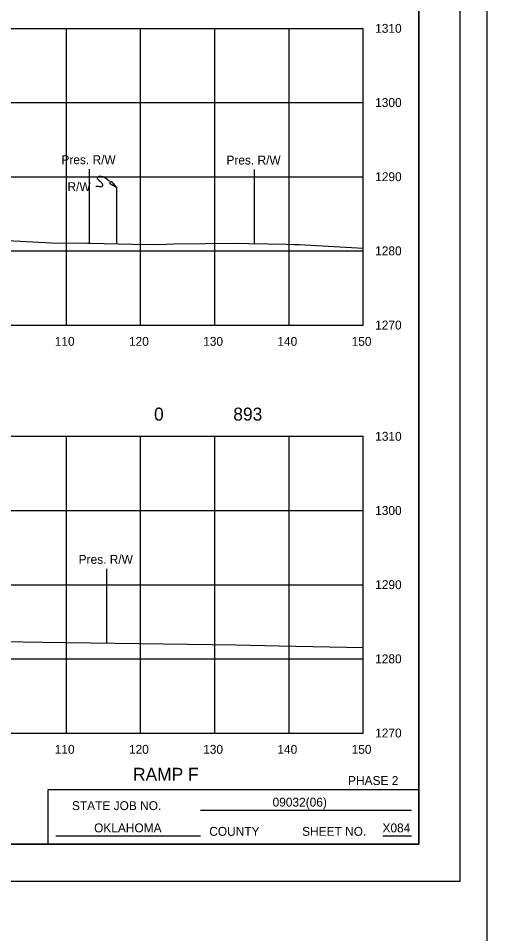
# Model space of a CAD drawing. Extents: x 2148105 to 2149976, y 144169 to 149705.
# Drawn here: x 2148516.8 to 2148579.9, y 144909.9 to 145033.3 of the extents above; entities that cross this region are included whole.
import ezdxf

# ---------------------------------------------------------------- set-up
doc = ezdxf.new("R2010")
doc.units = 0
for name, color, linetype in [('PH1a-PR-ServRd', 7, 'Continuous'), ('PR_Align_Ramp_A', 7, 'Continuous'), ('PR_Align_Ramp_E', 7, 'Continuous'), ('PR_Align_Ramp_F', 7, 'Continuous'), ('PR_Align_Ramp_J', 7, 'Continuous'), ('PR_Align_Retaining_Wall_C', 7, 'Continuous'), ('PR_Storm_Conc_Box_PH1B', 7, 'Continuous'), ('PR_Storm_Conc_Pipe_PH1B', 7, 'Continuous'), ('PR_Storm_Inlet_CICI_PH1B', 7, 'Continuous'), ('PR_Storm_MH_PH1A', 7, 'Continuous'), ('PR_Storm_MH_PH1B', 7, 'Continuous'), ('PR_Storm_Standard_Median_Drain_PH1B', 7, 'Continuous'), ('TOPO_BRIDGE_Low Beam', 7, 'Continuous')]:
    doc.layers.add(name, color=color, linetype=linetype)

msp = doc.modelspace()

# ---------------------------------------------------------------- linework, layer by layer
at = {"layer": 'PH1a-PR-ServRd'}
for p, q in [((2148520.88, 144921.91), (2148520.88, 144929.3)), ((2148520.88, 144929.3), (2148570.82, 144929.3))]:
    msp.add_line(p, q, dxfattribs=at)
msp.add_lwpolyline([(2148570.82, 144921.91), (2148255.82, 144921.91), (2148255.82, 145131.91), (2148570.82, 145131.91)], close=True, dxfattribs=at)
at = {"layer": 'PR_Align_Ramp_E'}
msp.add_lwpolyline([(2148219.95, 145145.16), (2148579.95, 145145.16), (2148579.95, 144905.16), (2148219.95, 144905.16)], close=True, dxfattribs=at)
at = {"layer": 'PR_Align_Ramp_J'}
msp.add_lwpolyline([(2148236.32, 145136.91), (2148576.32, 145136.91), (2148576.32, 144916.91), (2148236.32, 144916.91)], close=True, dxfattribs=at)
at = {"layer": 'PR_Align_Retaining_Wall_C'}
for p, q in [((2148541.37, 144926.52), (2148569.82, 144926.52)), ((2148521.88, 144923.05), (2148541.37, 144923.05)), ((2148565.97, 144923.05), (2148569.82, 144923.05))]:
    msp.add_line(p, q, dxfattribs=at)
at = {"layer": 'PR_Storm_Conc_Box_PH1B'}
for p, q in [((2148263.32, 145031.91), (2148563.32, 145031.91)), ((2148523.32, 144991.91), (2148523.32, 145031.91)), ((2148533.32, 144991.91), (2148533.32, 145031.91)), ((2148543.32, 144991.91), (2148543.32, 145031.91)), ((2148553.32, 144991.91), (2148553.32, 145031.91)), ((2148563.32, 144991.91), (2148563.32, 145031.91)), ((2148263.32, 145021.91), (2148563.32, 145021.91)), ((2148263.32, 145011.91), (2148563.32, 145011.91)), ((2148263.32, 145001.91), (2148563.32, 145001.91)), ((2148263.32, 144991.91), (2148563.32, 144991.91)), ((2148263.32, 144976.91), (2148563.32, 144976.91)), ((2148523.32, 144936.91), (2148523.32, 144976.91)), ((2148533.32, 144936.91), (2148533.32, 144976.91)), ((2148543.32, 144936.91), (2148543.32, 144976.91)), ((2148553.32, 144936.91), (2148553.32, 144976.91)), ((2148563.32, 144936.91), (2148563.32, 144976.91)), ((2148263.32, 144966.91), (2148563.32, 144966.91)), ((2148263.32, 144956.91), (2148563.32, 144956.91)), ((2148263.32, 144946.91), (2148563.32, 144946.91)), ((2148263.32, 144936.91), (2148563.32, 144936.91))]:
    msp.add_line(p, q, dxfattribs=at)
at = {"layer": 'PR_Storm_Conc_Pipe_PH1B'}
msp.add_lwpolyline([(2148255.82, 144921.91), (2148570.82, 144921.91), (2148570.82, 145131.91), (2148255.82, 145131.91)], close=True, dxfattribs=at)
msp.add_lwpolyline([(2148255.82, 144921.91), (2148570.82, 144921.91), (2148570.82, 145131.91), (2148255.82, 145131.91)], close=True, dxfattribs=at)
at = {"layer": 'PR_Storm_Inlet_CICI_PH1B'}
for points in [[(2148513.64, 145003.39), (2148521.31, 145003.01), (2148526.18, 145002.94), (2148526.53, 145002.93), (2148532.23, 145002.83), (2148535.83, 145002.79), (2148537.81, 145002.84), (2148546.22, 145002.93), (2148547.9, 145002.9), (2148553.04, 145002.8), (2148554.01, 145002.77), (2148554.69, 145002.76), (2148563.32, 145002.27)], [(2148383.92, 144951.36), (2148393.36, 144951.11), (2148395.33, 144950.69), (2148395.77, 144950.58), (2148397.19, 144950.58), (2148404.66, 144950.58), (2148427.82, 144950.58), (2148427.82, 144950.58), (2148428.89, 144950.55), (2148429.62, 144950.53), (2148458.36, 144949.75), (2148458.82, 144949.84), (2148460.86, 144950.23), (2148465.15, 144950.18), (2148481.59, 144949.82), (2148493.11, 144949.63), (2148504.69, 144949.36), (2148514.84, 144949.25), (2148520.1, 144949.18), (2148546.13, 144948.8), (2148552.01, 144948.65), (2148563.32, 144948.42)]]:
    msp.add_lwpolyline(points, dxfattribs=at)
at = {"layer": 'PR_Storm_MH_PH1A'}
for p, q in [((2148526.45, 145002.94), (2148526.45, 145012.94)), ((2148548.68, 145002.88), (2148548.68, 145012.88)), ((2148528.77, 144949.06), (2148528.77, 144959.06))]:
    msp.add_line(p, q, dxfattribs=at)
at = {"layer": 'PR_Storm_Standard_Median_Drain_PH1B'}
for p, q in [((2148563.32, 144991.91), (2148563.32, 145031.91)), ((2148263.32, 144991.91), (2148563.32, 144991.91)), ((2148563.32, 144936.91), (2148563.32, 144976.91)), ((2148263.32, 144936.91), (2148563.32, 144936.91))]:
    msp.add_line(p, q, dxfattribs=at)
at = {"layer": 'TOPO_BRIDGE_Low Beam'}
msp.add_line((2148530.13, 145002.87), (2148530.13, 145010.47), dxfattribs=at)
for points in [[(2148529.12, 145011.28), (2148528.77, 145011.57), (2148528.6, 145011.7), (2148528.51, 145011.77), (2148528.41, 145011.83), (2148528.31, 145011.88), (2148528.19, 145011.91), (2148528.06, 145011.94), (2148527.97, 145011.95), (2148527.88, 145011.95), (2148527.8, 145011.95), (2148527.73, 145011.93), (2148527.68, 145011.92), (2148527.62, 145011.9), (2148527.58, 145011.87), (2148527.54, 145011.84), (2148527.51, 145011.8), (2148527.48, 145011.74), (2148527.48, 145011.68), (2148527.49, 145011.64), (2148527.54, 145011.57), (2148527.73, 145011.41), (2148527.92, 145011.25), (2148528, 145011.17), (2148528.06, 145011.1), (2148528.12, 145011), (2148528.16, 145010.94), (2148528.2, 145010.85), (2148528.2, 145010.78), (2148528.18, 145010.69), (2148528.14, 145010.62), (2148528.09, 145010.59), (2148528.03, 145010.56), (2148527.92, 145010.55), (2148527.79, 145010.56), (2148527.63, 145010.57), (2148527.3, 145010.61)], [(2148530.13, 145010.47), (2148529.61, 145011.02), (2148529.35, 145011.33), (2148529.27, 145011.16), (2148529.13, 145011.04), (2148530.13, 145010.47)]]:
    msp.add_lwpolyline(points, dxfattribs=at)

# ---------------------------------------------------------------- texts
at = {"layer": 'PR_Align_Ramp_A'}
for s, p in [('0', (2148535.13, 144979.03)), ('893', (2148545.81, 144979.03))]:
    msp.add_text(s, height=1.75, dxfattribs=at).set_placement(p)
at = {"layer": 'PR_Align_Ramp_F'}
for s, height, p in [('RAMP F', 1.75, (2148532.3, 144930.47)), ('PHASE 2', 1.2, (2148561.27, 144929.9)), ('09032(06)', 1.2, (2148551.1, 144926.99)), ('STATE JOB NO.', 1.2, (2148524.07, 144926.52)), ('OKLAHOMA', 1.2, (2148527.05, 144923.52)), ('COUNTY', 1.2, (2148542.57, 144923.05)), ('SHEET NO.', 1.2, (2148555.08, 144923.05)), ('X084', 1.2, (2148565.91, 144923.52))]:
    msp.add_text(s, height=height, dxfattribs=at).set_placement(p)
at = {"layer": 'PR_Storm_MH_PH1A'}
for p in [(2148522.65, 145013.6), (2148544.88, 145013.55), (2148524.97, 144959.72)]:
    msp.add_text('Pres. R/W', height=1.2, rotation=360, dxfattribs=at).set_placement(p)
at = {"layer": 'PR_Storm_MH_PH1B'}
for s, p in [('1310', (2148564.92, 145031.31)), ('1300', (2148564.92, 145021.31)), ('1290', (2148564.92, 145011.31)), ('1280', (2148564.92, 145001.31)), ('1270', (2148564.92, 144991.31)), ('110', (2148521.75, 144989.11)), ('120', (2148531.75, 144989.11)), ('130', (2148541.75, 144989.11)), ('140', (2148551.75, 144989.11)), ('150', (2148561.75, 144989.11)), ('1310', (2148564.92, 144976.31)), ('1300', (2148564.92, 144966.31)), ('1290', (2148564.92, 144956.31)), ('1280', (2148564.92, 144946.31)), ('1270', (2148564.92, 144936.31)), ('110', (2148521.75, 144934.11)), ('120', (2148531.75, 144934.11)), ('130', (2148541.75, 144934.11)), ('140', (2148551.75, 144934.11)), ('150', (2148561.75, 144934.11))]:
    msp.add_text(s, height=1.2, dxfattribs=at).set_placement(p)
at = {"layer": 'TOPO_BRIDGE_Low Beam'}
msp.add_text('R/W', height=1.2, rotation=360, dxfattribs=at).set_placement((2148523.47, 145009.97))

doc.saveas('drawing.dxf')
